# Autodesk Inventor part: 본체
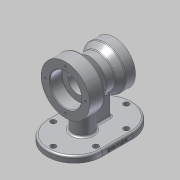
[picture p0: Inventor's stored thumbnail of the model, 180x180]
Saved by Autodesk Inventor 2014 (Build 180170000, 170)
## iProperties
Created: 2020-01
Part Number: 본체
Material: Aluminum 6061
Document SubType Name: Modeling
Designer: kh
Density: 2.71 g/cm^3
Appearance: Aluminum - Flat
Author: kh
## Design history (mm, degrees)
sketch "Sketch1"
  geometry: L1 (0, 45)-(50, 45); L2 (50, -45)-(0, -45); A1 r 45 centre (0, 0) between (0, 45) and (0, -45); A2 r 45 centre (50, 0) between (50, -45) and (50, 45); 1 further point
  constraints: 4 end point, 4 point on circle, 2 centre point, 2 tangent, 1 coincident, 1 horizontal alignment, 1 parallel
  dimensions: "d0" = 45 radius of A1; "d1" = 45 radius of A2; "d2" = 50 distance of A2.centre point (0, 0)
extrude "Extrusion1" new body sketch "Sketch1" distance "d3" = 10; taper "d4" = 0 deg
sketch "Sketch2"
  geometry: L1 (0, 45)-(-50, 45) reference; L2 (-50, -45)-(0, -45) reference; L3 (-50, 35)-(0, 35); L4 (0, -35)-(-50, -35); A1 r 45 centre (-50, 0) between (-50, 45) and (-50, -45) reference; A2 r 45 centre (0, 0) between (0, -45) and (0, 45) reference; A3 r 35 centre (-50, 0) between (-50, 35) and (-50, -35); A4 r 35 centre (0, 0) between (0, -35) and (0, 35); 6 further points
  constraints: 6 point on circle, 4 coincident, 4 end point, 2 centre point, 3 other
  dimensions: "d5" = 10 distance between parallel lines of L1 L3
hole "Hole1" sketch "Sketch2" at (-50, 35), (-85, 0), (-50, -35), (0, -35), (35, 0), (0, 35) diameter "d6" = 9; stored, may be unused: countersink angle "d10" = 90 deg, drill point angle "d12" = 118 deg; dims "d7" = 6, "d8" = 4, "d9" = 2, "d11" = 8
sketch "Sketch3"
  geometry: L1 (-21.801, -5)-(5, -5); L2 (5, -5)-(5, 5); L3 (5, 5)-(-21.801, 5); L4 (-5, -5)-(5, 5); L5 (5, -5)-(-5, 5); A1 r 45 centre (-50, 0) between (-50, 45) and (-50, -45) reference; A2 r 45 centre (0, 0) between (0, -45) and (0, 45) reference; A3 r 16 centre (-37, 0) between (-21.801, 5) and (-21.801, -5); 2 further points
  constraints: 10 end point, 4 point on circle, 2 midpoint, 2 point on line, 1 centre point, 1 horizontal, 1 parallel, 1 perpendicular
  dimensions: "d13" = 16 radius of A3; "d14" = 58 distance of A3.centre point (-95, 0); "d15" = 40 distance from line of point (45, 0) L2; "d16" = 10 distance of L1.end L2.end
extrude "Extrusion2" join sketch "Sketch3" distance "d17" = 70; taper "d18" = 0 deg
workplane "Work Plane1"
sketch "Sketch4"
  geometry: L1 (0, 10)-(-45, 10) reference; L2 (-45, 0)-(-45, 10) reference; L3 (-3, 10)-(-3, 80) reference; L4 (55, 10)-(55, 80) reference; L5 (95, 0)-(95, 10) reference; L6 (0, 0)-(-45, 0) reference; L7 (28.199, 80)-(-3, 80) reference; L8 (-15, 80)-(-15, 120); L9 (-15, 80)-(65, 80); L10 (-15, 120)-(9, 120); L11 (9, 120)-(23.897, 107.5); L12 (-43.813, 107.5)-(135.116, 107.5); L13 (65, 80)-(65, 115); L14 (65, 115)-(49, 115); L15 (49, 115)-(38.289, 107.5); L16 (23.897, 107.5)-(38.289, 107.5); 1 further point
  constraints: 18 end point, 4 perpendicular, 2 parallel, 2 point on line, 1 collinear
  dimensions: "d19" = 80 distance between parallel lines of L6 L7 (derived); "d20" = 40 distance of L8.start L8.end; "d21" = 30 distance between parallel lines of L2 L8; "d22" = 80 distance of L8.start L9.end; "d23" = 24 distance of L8.end L10.end; "d24" = 55 diameter of L12 L9; "d26" = 35 distance of L9.end L13.end; "d27" = 16 distance of L13.end L14.end; "d29" = 40 deg angle of L12 L11; "d30" = 35 deg angle of L12 L15
revolve "Revolution1" sketch "Sketch4" stored, may be unused: angle "d31" = 90 deg
hole "Hole2" diameter "d34" = 32; stored, may be unused: countersink angle "d38" = 90 deg, drill point angle "d40" = 118 deg; dims "d32" = 10, "d33" = 10, "d35" = 6, "d36" = 4, "d37" = 2, "d39" = 8
hole "Hole3" diameter "d43" = 52; stored, may be unused: countersink angle "d47" = 90 deg, drill point angle "d49" = 0 deg; dims "d41" = 10, "d42" = 10, "d44" = 6, "d45" = 4, "d46" = 2, "d48" = 20
hole "Hole4" diameter "d52" = 40; stored, may be unused: countersink angle "d56" = 90 deg, drill point angle "d58" = 0 deg; dims "d50" = 10, "d51" = 10, "d53" = 6, "d54" = 4, "d55" = 2, "d57" = 18
fillet "Fillet1" dims "d59" = 0.3
fillet "Fillet2" dims "d60" = 3
chamfer "Chamfer1" distance "d61" = 1; stored, may be unused: second distance "d62" = 2, angle "d63" = 45 deg
fillet "Fillet3" dims "d64" = 3
sketch "Sketch6" dims "d68" = 33
  geometry: C1 r 27 at (0, 0) reference; 3 further points
  constraints: 1 coincident, 1 vertical alignment, 2 other
hole "Hole5" sketch "Sketch6" at (0, 33) diameter "d69" = 3.242; stored, may be unused: countersink angle "d73" = 90 deg, drill point angle "d75" = 118 deg; dims "d70" = 9, "d71" = 4, "d72" = 2, "d74" = 11
pattern_circular "Circular Pattern1" dims angle "d77" = 360 deg
sketch "Sketch7" dims "d79" = 27.5
  geometry: C1 r 21 at (0, 0) reference; 3 further points
  constraints: 1 coincident, 1 vertical alignment, 2 other
hole "Hole6" sketch "Sketch7" at (0, 27.5) diameter "d80" = 3.242; stored, may be unused: countersink angle "d84" = 90 deg, drill point angle "d86" = 118 deg; dims "d81" = 9, "d82" = 4, "d83" = 2, "d85" = 11
pattern_circular "Circular Pattern2" dims angle "d88" = 360 deg
sketch "Sketch8"
  geometry: L1 (0, 0)-(50, 0) reference; L2 (-45, 0)-(-45, 7) reference; 1 further point
  constraints: 1 other
  dimensions: "d90" = 4 distance from line of L1 point (25, 4); "d91" = 70 distance from line of point (25, 4) L2
emboss "Emboss1" sketch "Sketch8" dims "d0" = 45, "d1" = 45, "d2" = 50, "d92" = 0.5, "d93" = 0
body "Solid1"
